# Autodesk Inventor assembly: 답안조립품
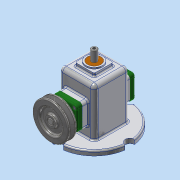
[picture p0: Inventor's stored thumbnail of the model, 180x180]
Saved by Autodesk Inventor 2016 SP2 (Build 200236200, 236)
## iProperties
Created: 2018-07
Part Number: 답안조립품
Document SubType Name: Assembly
Designer: Administrator
Author: Administrator
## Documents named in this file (15)
- Z:\인벤터기술자격증시험\480707V1009 오성민\480707V1009\답안조립품.iam
- Z:\인벤터기술자격증시험\480707V1009 오성민\480707V1009\본체.ipt
- Z:\인벤터기술자격증시험\480707V1009 오성민\480707V1009\V벨트풀리.ipt
- Z:\인벤터기술자격증시험\480707V1009 오성민\480707V1009\고정핀 1.2x8.ipt
- Z:\인벤터기술자격증시험\480707V1009 오성민\480707V1009\뒤커버.ipt
- Z:\인벤터기술자격증시험\480707V1009 오성민\480707V1009\링크.ipt
- Z:\인벤터기술자격증시험\480707V1009 오성민\480707V1009\베어링 12x32x10.ipt
- Z:\인벤터기술자격증시험\480707V1009 오성민\480707V1009\볼트 M4.ipt
- Z:\인벤터기술자격증시험\480707V1009 오성민\480707V1009\부시.ipt
- Z:\인벤터기술자격증시험\480707V1009 오성민\480707V1009\슬라이드.ipt
- Z:\인벤터기술자격증시험\480707V1009 오성민\480707V1009\앞커버.ipt
- Z:\인벤터기술자격증시험\480707V1009 오성민\480707V1009\오일 실 12 25 7.ipt
- Z:\인벤터기술자격증시험\480707V1009 오성민\480707V1009\키 4x4x10.ipt
- Z:\인벤터기술자격증시험\480707V1009 오성민\480707V1009\편심축.ipt
- Z:\인벤터기술자격증시험\480707V1009 오성민\480707V1009\핀 5x18.ipt
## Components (3 placed, 3 different names)
1. V벨트풀리:1 — 각도:2
2. 고정핀 1.2x8:1
3. 핀 5x18:1
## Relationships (1: Angle 1)
- 각도:2 [Angle]: V벨트풀리:1
